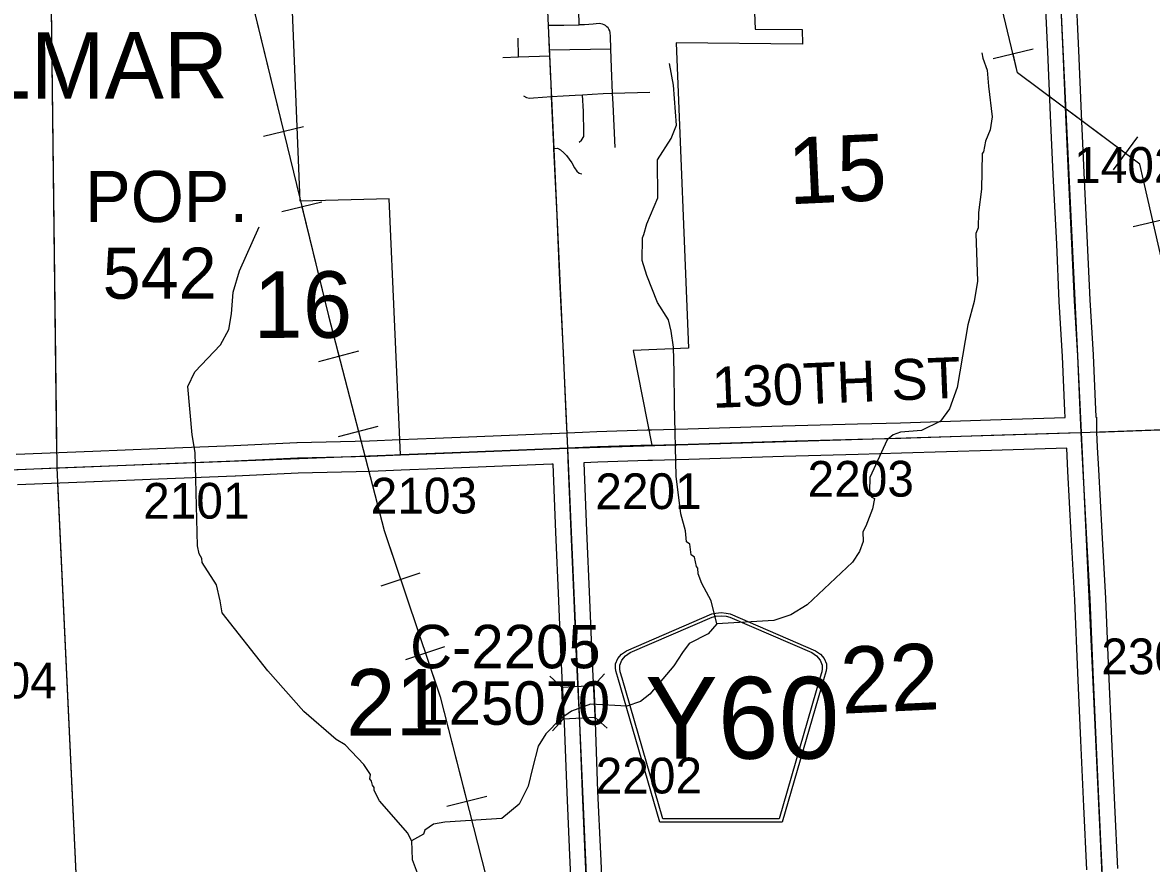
# Model space of a CAD drawing. Extents: x 128.7 to 185.5, y -21.4 to 12.6.
# Drawn here: x 147.811 to 150.021, y 0.955 to 2.6 of the extents above; entities that cross this region are included whole.
import ezdxf

# ---------------------------------------------------------------- set-up
doc = ezdxf.new("R2010")
doc.units = 0
for name, color, linetype in [('tdCoCityStreetMajor', 7, 'Continuous'), ('tdCoCityStreetMinor', 7, 'Continuous'), ('tdCoCorpBndry', 7, 'Continuous'), ('tdCoCorpPopTxt', 7, 'Continuous'), ('tdCoCorpTxt', 7, 'Continuous'), ('tdCoHydroRiver', 7, 'Continuous'), ('tdCoPipe', 7, 'Continuous'), ('tdCoSecRdNmbr', 7, 'Continuous'), ('tdCoSecRdTxt', 7, 'Continuous'), ('tdCoSecRteBand', 7, 'Continuous'), ('tdCoSecRteCL', 7, 'Continuous'), ('tdCoSectLine', 7, 'Continuous'), ('tdCoSectLinePart', 7, 'Continuous'), ('tdCoSectNmbr', 7, 'Continuous'), ('tdCoShieldCoRteHrd', 7, 'Continuous'), ('tdCoStrucSec', 7, 'Continuous'), ('tdCoStrucSecCoName', 7, 'Continuous'), ('tdCoStrucSecFHWANum', 7, 'Continuous'), ('tdCoSurfAsphalt', 7, 'Continuous'), ('tdCoSurfGravel', 7, 'Continuous')]:
    doc.layers.add(name, color=color, linetype=linetype)

msp = doc.modelspace()

# ---------------------------------------------------------------- linework, layer by layer
at = {"layer": 'tdCoCityStreetMajor'}
msp.add_lwpolyline([(148.8783, 1.7679), (148.8748, 1.8491), (148.8699, 1.9547), (148.863, 2.0957), (148.8591, 2.1909), (148.8578, 2.2232), (148.8511, 2.3544), (148.8509, 2.3584), (148.8503, 2.3717), (148.8467, 2.4558), (148.8455, 2.4846), (148.8452, 2.4906), (148.8431, 2.5355), (148.8425, 2.547), (148.8403, 2.5954), (148.8397, 2.6072)], dxfattribs=at)
at = {"layer": 'tdCoCityStreetMinor'}
for p, q in [((148.7817, 2.5334), (148.781, 2.5698)), ((148.8425, 2.547), (148.9627, 2.5494)), ((148.7512, 2.5323), (148.7817, 2.5334)), ((148.7817, 2.5334), (148.8431, 2.5355)), ((148.9661, 2.4621), (149.0392, 2.4645))]:
    msp.add_line(p, q, dxfattribs=at)
for points in [[(148.9007, 2.596), (148.9004, 2.6041), (148.8989, 2.6419), (148.8975, 2.6751)], [(148.8403, 2.5954), (148.8708, 2.5954), (148.9007, 2.596)], [(148.9627, 2.5494), (148.9618, 2.5732), (148.9615, 2.5814), (148.9605, 2.5845), (148.959, 2.5874), (148.9571, 2.5901), (148.9548, 2.5925), (148.9528, 2.5941), (148.9522, 2.5946), (148.9494, 2.5962), (148.9463, 2.5974), (148.9431, 2.5981), (148.9398, 2.5984), (148.9277, 2.5976), (148.911, 2.5962), (148.9007, 2.596)], [(148.9661, 2.4621), (148.9642, 2.5121), (148.9627, 2.5494)], [(148.7916, 2.4573), (148.7973, 2.4539), (148.8034, 2.4529), (148.811, 2.4534), (148.8467, 2.4558), (148.869, 2.4573), (148.893, 2.4586), (148.9069, 2.4593)], [(148.9003, 2.3668), (148.9053, 2.3702), (148.9095, 2.3774), (148.9099, 2.3848), (148.909, 2.4265), (148.9069, 2.4593)], [(148.9069, 2.4593), (148.9258, 2.4604), (148.9477, 2.4615), (148.9661, 2.4621)], [(148.9711, 2.3562), (148.9669, 2.4406), (148.9661, 2.4621)], [(148.8511, 2.3544), (148.8579, 2.3547), (148.8643, 2.3513), (148.8707, 2.3456), (148.8759, 2.3402), (148.8865, 2.3259), (148.8915, 2.316), (148.8959, 2.3096), (148.9003, 2.3061), (148.9055, 2.3044)]]:
    msp.add_lwpolyline(points, dxfattribs=at)
at = {"layer": 'tdCoCorpBndry'}
msp.add_lwpolyline([(149.2374, 2.7846), (149.245, 2.5877), (149.3373, 2.5868), (149.338, 2.5584), (149.0904, 2.5606), (149.1146, 1.9632), (149.0066, 1.959), (149.0431, 1.7736), (148.9363, 1.7702), (148.8783, 1.7679), (148.6852, 1.7601), (148.551, 1.7548), (148.5286, 2.2555), (148.3545, 2.2508), (148.3339, 2.752)], dxfattribs=at)
at = {"layer": 'tdCoHydroRiver'}
for points in [[(149.6888, 2.5416), (149.6908, 2.5306), (149.6995, 2.5073), (149.7021, 2.4758), (149.7089, 2.4161), (149.7051, 2.3907), (149.6963, 2.3683), (149.6923, 2.3476), (149.6893, 2.3444), (149.6885, 2.2749), (149.6822, 2.2289), (149.6816, 2.1989), (149.6773, 2.1877), (149.6805, 2.0947), (149.674, 2.0551), (149.6613, 2.0089), (149.6403, 1.8866), (149.6259, 1.8451), (149.6078, 1.8208), (149.5706, 1.8022), (149.5297, 1.7992), (149.5156, 1.794), (149.5034, 1.7841), (149.4696, 1.7103), (149.4689, 1.6835), (149.4738, 1.6789), (149.4725, 1.6726), (149.4789, 1.6696), (149.4749, 1.649), (149.4618, 1.6154), (149.4559, 1.6041), (149.4565, 1.5852), (149.4493, 1.566), (149.4358, 1.5451), (149.3472, 1.4615), (149.3147, 1.4415), (149.2819, 1.4309), (149.1701, 1.4239), (149.1534, 1.4044), (149.1162, 1.3857), (149.1026, 1.3679), (149.0861, 1.3421), (149.0391, 1.2868), (149.0207, 1.272), (148.9942, 1.2632), (148.923, 1.2671), (148.8856, 1.2531), (148.864, 1.2382), (148.8351, 1.2088), (148.8201, 1.1846), (148.809, 1.1416), (148.8007, 1.1066), (148.783, 1.0713), (148.7492, 1.0433), (148.6374, 1.0363), (148.6154, 1.0324), (148.5985, 1.0208), (148.5956, 1.0128), (148.5724, 0.9994), (148.5736, 0.9631), (148.5857, 0.932)], [(149.1701, 1.4239), (149.1591, 1.4693), (149.1406, 1.5034), (149.1336, 1.5221), (149.1332, 1.5331), (149.13, 1.5361), (149.1262, 1.5549), (149.1197, 1.5594), (149.1174, 1.5799), (149.111, 1.5844), (149.1086, 1.6064), (149.0996, 1.6392), (149.0908, 1.7131), (149.0875, 1.855), (149.0869, 1.9166), (149.0853, 1.9654), (149.081, 1.9968), (149.0755, 2.0187), (149.0539, 2.0527), (149.0331, 2.1056), (149.0242, 2.1353), (149.0243, 2.1795), (149.0272, 2.1859), (149.0328, 2.2066), (149.0547, 2.2579), (149.0537, 2.332), (149.0807, 2.374), (149.0909, 2.3996), (149.085, 2.4783), (149.0772, 2.5206)], [(148.5724, 0.9994), (148.5655, 1.0149), (148.5097, 1.0777), (148.4996, 1.0979), (148.4993, 1.1042), (148.496, 1.1088), (148.4942, 1.1166), (148.4909, 1.1212), (148.4922, 1.1292), (148.4789, 1.1492), (148.4428, 1.1875), (148.4251, 1.1979), (148.3617, 1.2525), (148.2911, 1.3322), (148.202, 1.4459), (148.198, 1.4694), (148.1906, 1.5007), (148.1623, 1.5439), (148.1621, 1.5518), (148.157, 1.5611), (148.1533, 1.5768), (148.1486, 1.7597), (148.1427, 1.7942), (148.1347, 1.8886), (148.1479, 1.9175), (148.1982, 1.9697), (148.2145, 2.0002), (148.2198, 2.0304), (148.2231, 2.0731), (148.2359, 2.1146), (148.2739, 2.2011)]]:
    msp.add_lwpolyline(points, dxfattribs=at)
at = {"layer": 'tdCoPipe'}
for p, q in [((149.7893, 2.5487), (149.7109, 2.5299)), ((148.2826, 2.3784), (148.3609, 2.3974)), ((149.9939, 2.3771), (149.9457, 2.3127)), ((148.3185, 2.2306), (148.3967, 2.2496)), ((150.0635, 2.219), (149.9849, 2.2009)), ((148.3911, 1.9377), (148.4691, 1.958)), ((148.4294, 1.7905), (148.5073, 1.8108)), ((148.5128, 1.4984), (148.5892, 1.5241)), ((148.5613, 1.3543), (148.6376, 1.3799)), ((148.6415, 1.0673), (148.7196, 1.0872))]:
    msp.add_line(p, q, dxfattribs=at)
for points in [[(153.2907, -13.3487), (153.1504, -13.0403), (153.08, -11.9742), (153.9221, -10.7441), (153.8422, -9.1961), (152.4885, -6.1792), (152.255, -4.5804), (152.0586, -4.5041), (150.9187, -1.6917), (149.9982, 2.3236), (149.759, 2.5022), (149.1601, 4.9961)], [(147.8878, 4.8774), (147.8987, 4.5052), (147.9615, 4.1897), (147.957, 3.3831), (148.1979, 2.8974), (148.4096, 2.0269), (148.5189, 1.6067), (148.6284, 1.2813), (148.7667, 0.7397)], [(148.2506, 2.6805), (148.3218, 2.3879)], [(149.9698, 2.3448), (149.759, 2.5022), (149.7501, 2.5393)], [(148.3577, 2.2401), (148.4096, 2.0269), (148.4301, 1.9479)], [(148.4684, 1.8007), (148.5189, 1.6067), (148.551, 1.5113)], [(148.5995, 1.3671), (148.6284, 1.2813), (148.6805, 1.0773)]]:
    msp.add_lwpolyline(points, dxfattribs=at)
at = {"layer": 'tdCoSecRteBand'}
for points in [[(147.7987, 1.7558), (147.9484, 1.762), (148.0748, 1.7674), (148.0749, 1.7674), (148.075, 1.7674), (148.2248, 1.7728), (148.3479, 1.779), (148.3482, 1.779), (148.3486, 1.779), (148.4902, 1.7825), (148.5498, 1.7848), (148.6185, 1.7875), (148.6841, 1.7901), (148.8448, 1.7965), (148.8471, 1.7966), (148.877, 1.7978), (148.907, 1.7991), (148.907, 1.7991), (148.907, 1.7991), (148.9351, 1.8002), (148.9352, 1.8002), (148.9353, 1.8002), (149.0335, 1.8034), (149.0336, 1.8034), (149.0337, 1.8034), (149.0423, 1.8036), (149.1131, 1.8059), (149.1131, 1.8059), (149.1132, 1.8059), (149.2989, 1.8116), (149.2989, 1.8116), (149.299, 1.8116), (149.4452, 1.8155), (149.4452, 1.8155), (149.4452, 1.8155), (149.5297, 1.8177), (149.706, 1.8234), (149.706, 1.8234), (149.706, 1.8234), (149.8519, 1.8279), (149.8512, 1.8406), (149.8512, 1.8408), (149.8512, 1.841), (149.847, 1.9472), (149.8404, 2.0546), (149.8404, 2.0548), (149.8404, 2.0551), (149.8354, 2.1668), (149.8288, 2.3036), (149.8288, 2.3036), (149.8288, 2.3036), (149.8234, 2.419), (149.8234, 2.4191), (149.8233, 2.4192), (149.8182, 2.5434), (149.8125, 2.67)], [(149.8724, 2.6728), (149.8781, 2.5461), (149.8781, 2.546), (149.8781, 2.546), (149.8833, 2.4218), (149.8887, 2.3064), (149.8954, 2.1696), (149.8954, 2.1695), (149.8954, 2.1695), (149.9003, 2.058), (149.9069, 1.9505), (149.907, 1.9502), (149.907, 1.9498), (149.9112, 1.8435), (149.9119, 1.8298), (149.9119, 1.8285), (149.9133, 1.8285), (149.9135, 1.7992), (149.915, 1.7699), (149.9173, 1.7258), (149.9173, 1.7258), (149.9173, 1.7258), (149.9235, 1.6033), (149.9311, 1.474), (149.9311, 1.4737), (149.9311, 1.4735), (149.9371, 1.3307), (149.943, 1.1989), (149.9489, 1.0694), (149.9489, 1.0694), (149.9489, 1.0693), (149.9543, 0.9456)], [(149.8944, 0.943), (149.8889, 1.0667), (149.883, 1.1961), (149.883, 1.1961), (149.883, 1.1962), (149.8771, 1.3281), (149.8771, 1.3281), (149.8771, 1.3282), (149.8712, 1.4707), (149.8636, 1.5999), (149.8636, 1.6001), (149.8636, 1.6002), (149.8574, 1.7227), (149.855, 1.768), (149.7079, 1.7634), (149.5316, 1.7578), (149.5315, 1.7578), (149.5314, 1.7578), (149.4468, 1.7555), (149.3006, 1.7516), (149.115, 1.7459), (149.0441, 1.7436), (149.0441, 1.7436), (149.0441, 1.7436), (149.0441, 1.7436), (149.044, 1.7436), (149.0439, 1.7436), (149.0353, 1.7434), (148.9374, 1.7403), (148.9095, 1.7391), (148.9149, 1.6058), (148.9208, 1.4719), (148.9208, 1.4719), (148.9208, 1.4718), (148.9255, 1.361), (148.9317, 1.2321), (148.9317, 1.2319), (148.9317, 1.2318), (148.9368, 1.0968), (148.9425, 0.9743), (148.9425, 0.9743), (148.9425, 0.9743), (148.9477, 0.8611)], [(148.8877, 0.8584), (148.8826, 0.9715), (148.8769, 1.0941), (148.8769, 1.0942), (148.8769, 1.0943), (148.8717, 1.2293), (148.8656, 1.3582), (148.8656, 1.3583), (148.8655, 1.3583), (148.8609, 1.4693), (148.8549, 1.6032), (148.8549, 1.6032), (148.8549, 1.6033), (148.8496, 1.7367), (148.8473, 1.7366), (148.8472, 1.7366), (148.8472, 1.7366), (148.6864, 1.7302), (148.6864, 1.7302), (148.6864, 1.7302), (148.6209, 1.7276), (148.5522, 1.7249), (148.4923, 1.7225), (148.4921, 1.7225), (148.4919, 1.7225), (148.3505, 1.719), (148.2276, 1.7129), (148.2274, 1.7129), (148.2271, 1.7129), (148.0773, 1.7075), (147.9509, 1.702), (147.9509, 1.702), (147.9508, 1.702), (147.8013, 1.6959)]]:
    msp.add_lwpolyline(points, dxfattribs=at)
at = {"layer": 'tdCoSecRteCL'}
for points in [[(149.8835, 1.7983), (149.8812, 1.8421), (149.877, 1.9487), (149.8703, 2.0564), (149.8654, 2.1681), (149.8587, 2.305), (149.8533, 2.4204), (149.8481, 2.5447), (149.8425, 2.6715), (149.8361, 2.7945), (149.8339, 2.8522), (149.8334, 2.8927), (149.8319, 2.9067)], [(148.8783, 1.7679), (148.9363, 1.7702), (149.0344, 1.7734), (149.0431, 1.7736), (149.0431, 1.7736), (149.1141, 1.7759), (149.2998, 1.7816), (149.446, 1.7855), (149.5306, 1.7877), (149.7069, 1.7934), (149.8586, 1.7981), (149.8835, 1.7983)], [(149.931, 0.7932), (149.9293, 0.8264), (149.9243, 0.9442), (149.9189, 1.068), (149.913, 1.1975), (149.9071, 1.3294), (149.9012, 1.4722), (149.8935, 1.6017), (149.8874, 1.7243), (149.8835, 1.7983)], [(147.4001, 1.7066), (147.4268, 1.7066), (147.5802, 1.715), (147.6769, 1.7199), (147.7999, 1.7258), (147.9496, 1.732), (148.0761, 1.7374), (148.2261, 1.7429), (148.3494, 1.749), (148.4912, 1.7525), (148.551, 1.7548), (148.6197, 1.7575), (148.6852, 1.7601), (148.846, 1.7665), (148.8783, 1.7679)], [(148.9216, 0.7682), (148.9204, 0.7983), (148.9177, 0.8597), (148.9125, 0.9729), (148.9069, 1.0955), (148.9017, 1.2306), (148.8955, 1.3596), (148.8908, 1.4706), (148.8849, 1.6045), (148.8792, 1.7451), (148.8783, 1.7679)]]:
    msp.add_lwpolyline(points, dxfattribs=at)
at = {"layer": 'tdCoSectLine'}
for points in [[(149.8352, 2.8073), (149.8831, 1.7983)], [(148.8323, 2.7663), (148.8779, 1.7679)], [(147.8658, 2.7381), (147.8779, 1.7291)], [(149.8831, 1.7983), (150.866, 1.8343)], [(148.8779, 1.7679), (149.8831, 1.7983)], [(149.8831, 1.7983), (149.9306, 0.7932)], [(147.8779, 1.7291), (148.8779, 1.7679)], [(148.8779, 1.7679), (148.9212, 0.7682)], [(146.882, 1.6866), (147.8779, 1.7291)], [(147.8779, 1.7291), (147.9248, 0.7278)]]:
    msp.add_lwpolyline(points, dxfattribs=at)
at = {"layer": 'tdCoSectLinePart'}
for points in [[(147.8658, 2.7381), (147.8775, 1.759)], [(149.9131, 1.7994), (150.836, 1.8332)], [(147.8793, 1.699), (147.9248, 0.7278)]]:
    msp.add_lwpolyline(points, dxfattribs=at)
at = {"layer": 'tdCoShieldCoRteHrd'}
for points in [[(149.0585, 1.036), (148.9766, 1.3189), (148.9727, 1.3321), (148.972, 1.338), (148.972, 1.3458), (148.9762, 1.3561), (148.9835, 1.3646), (148.9931, 1.3713), (149.1603, 1.4436), (149.1679, 1.4452), (149.1783, 1.4462), (149.1887, 1.4452), (149.1962, 1.4436), (149.3635, 1.3713), (149.3731, 1.3646), (149.3803, 1.3561), (149.3846, 1.3458), (149.3846, 1.338), (149.3839, 1.3321), (149.38, 1.3189), (149.298, 1.036)], [(149.0644, 1.0424), (148.9846, 1.3176), (148.9809, 1.3303), (148.9802, 1.3359), (148.9802, 1.3434), (148.9843, 1.3533), (148.9913, 1.3615), (149.0005, 1.3679), (149.1611, 1.4373), (149.1683, 1.4389), (149.1783, 1.4398), (149.1883, 1.4389), (149.1955, 1.4373), (149.3561, 1.3679), (149.3653, 1.3615), (149.3723, 1.3533), (149.3763, 1.3434), (149.3763, 1.3359), (149.3756, 1.3303), (149.3719, 1.3176), (149.2922, 1.0424)]]:
    msp.add_lwpolyline(points, close=True, dxfattribs=at)
at = {"layer": 'tdCoStrucSec'}
for p, q in [((148.9292, 1.3034), (148.9502, 1.3266)), ((148.8666, 1.3004), (148.8435, 1.3215)), ((148.8696, 1.2379), (148.8486, 1.2148)), ((148.9322, 1.2409), (148.9553, 1.2199))]:
    msp.add_line(p, q, dxfattribs=at)
msp.add_lwpolyline([(148.8696, 1.2379), (148.8666, 1.3004), (148.9292, 1.3034), (148.9322, 1.2409)], close=True, dxfattribs=at)
at = {"layer": 'tdCoSurfAsphalt'}
msp.add_lwpolyline([(148.9177, 0.8597), (148.9125, 0.9729), (148.9069, 1.0955), (148.9017, 1.2306), (148.8955, 1.3596), (148.8908, 1.4706), (148.8849, 1.6045), (148.8792, 1.7451), (148.8783, 1.7679)], dxfattribs=at)
at = {"layer": 'tdCoSurfGravel'}
msp.add_line((149.0431, 1.7736), (149.0431, 1.7736), dxfattribs=at)
for points in [[(149.931, 0.7932), (149.9293, 0.8264), (149.9243, 0.9442), (149.9189, 1.068), (149.913, 1.1975), (149.9071, 1.3294), (149.9012, 1.4722), (149.8935, 1.6017), (149.8874, 1.7243), (149.8835, 1.7983), (149.8812, 1.8421), (149.877, 1.9487), (149.8703, 2.0564), (149.8654, 2.1681), (149.8587, 2.305), (149.8533, 2.4204), (149.8481, 2.5447), (149.8425, 2.6715), (149.8361, 2.7945), (149.8339, 2.8522), (149.8334, 2.8927), (149.8319, 2.9067)], [(149.0431, 1.7736), (149.1141, 1.7759), (149.2998, 1.7816), (149.446, 1.7855), (149.5306, 1.7877), (149.7069, 1.7934), (149.8586, 1.7981), (149.8835, 1.7983)], [(148.551, 1.7548), (148.6197, 1.7575), (148.6852, 1.7601), (148.846, 1.7665), (148.8783, 1.7679), (148.9363, 1.7702), (149.0344, 1.7734), (149.0431, 1.7736)], [(147.4001, 1.7066), (147.4268, 1.7066), (147.5802, 1.715), (147.6769, 1.7199), (147.7999, 1.7258), (147.9496, 1.732), (148.0761, 1.7374), (148.2261, 1.7429), (148.3494, 1.749), (148.4912, 1.7525), (148.551, 1.7548)]]:
    msp.add_lwpolyline(points, dxfattribs=at)

# ---------------------------------------------------------------- texts
at = {"layer": 'tdCoCorpPopTxt'}
for s, p in [('POP.', (147.9335, 2.2102)), ('542', (147.9678, 2.0602))]:
    msp.add_text(s, height=0.1, dxfattribs=at).set_placement(p)
at = {"layer": 'tdCoCorpTxt'}
msp.add_text('DELMAR', height=0.13, rotation=0.1124, dxfattribs=at).set_placement((147.4888, 2.4508))
at = {"layer": 'tdCoSecRdNmbr'}
for s, rotation, p in [('1402', 0.114, (149.8696, 2.2867)), ('2203', 0.1136, (149.3478, 1.6727)), ('2103', 0.1129, (148.4925, 1.6398)), ('2201', 0.1133, (148.9323, 1.6484)), ('2101', 0.1126, (148.0471, 1.6297)), ('2302', 0.114, (149.9229, 1.3254)), ('2004', 0.1123, (147.6697, 1.2781)), ('2202', 0.1132, (148.933, 1.092))]:
    msp.add_text(s, height=0.07, rotation=rotation, dxfattribs=at).set_placement(p)
at = {"layer": 'tdCoSecRdTxt'}
msp.add_text('130TH ST', height=0.08, rotation=2.3766, dxfattribs=at).set_placement((149.1622, 1.8464))
at = {"layer": 'tdCoSectNmbr'}
for s, rotation, p in [('15', 2.6659, (149.3117, 2.2448)), ('16', 0.1129, (148.2629, 1.9836)), ('22', 2.666, (149.415, 1.2482)), ('21', 0.1128, (148.4444, 1.2055))]:
    msp.add_text(s, height=0.13, rotation=rotation, dxfattribs=at).set_placement(p)
at = {"layer": 'tdCoShieldCoRteHrd'}
msp.add_text('Y60', height=0.16, dxfattribs=at).set_placement((149.0294, 1.1603))
at = {"layer": 'tdCoStrucSecCoName'}
msp.add_text('C-2205', height=0.085, dxfattribs=at).set_placement((148.5697, 1.3372))
at = {"layer": 'tdCoStrucSecFHWANum'}
msp.add_text('125070', height=0.085, dxfattribs=at).set_placement((148.582, 1.2267))

doc.saveas('drawing.dxf')
